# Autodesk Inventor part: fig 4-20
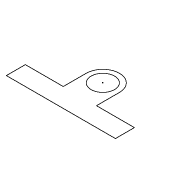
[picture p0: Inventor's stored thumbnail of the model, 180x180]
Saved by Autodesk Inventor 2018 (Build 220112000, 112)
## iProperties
Created: 2004-05
Part Number: fig 4-20
Document SubType Name: Modeling
Designer: CADCIM Technologies
Manufacturer: Standard
Standards Organization: Custom
Density: 1 g/cm^3
Material: Generic
Appearance: Default
Author: CADCIM Technologies
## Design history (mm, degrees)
sketch "Sketch1"
  geometry: L1 (21.396, 25)-(21.396, 15.181); L2 (21.396, 15.181)-(77.829, 15.181); L3 (77.829, 15.181)-(77.829, 25); L4 (77.829, 25)-(58.204, 25); L5 (58.204, 25)-(58.204, 36.886); L6 (41.021, 36.886)-(41.021, 25); L7 (41.021, 25)-(21.396, 25); C1 r 6.072 at (49.612, 36.886); A1 r 8.592 centre (49.612, 36.886) between (58.204, 36.886) and (41.021, 36.886)
  constraints: 14 end point, 5 parallel, 2 centre point, 2 equal length, 2 point on circle, 2 tangent, 1 coincident, 1 perpendicular, 1 vertical, 1 other
